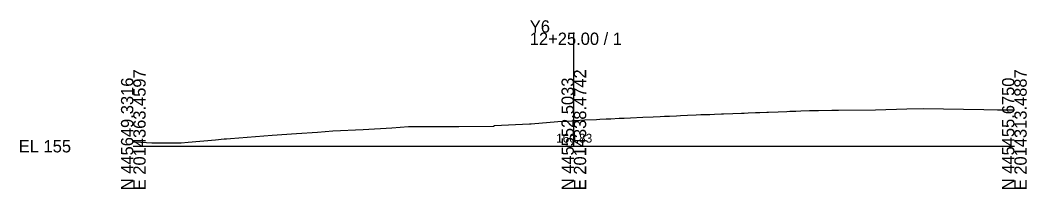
# Model space of a CAD drawing. Extents: x -26 to 203, y -10 to 4529.
# Drawn here: x -25.7 to 202.8, y 4490.3 to 4528.7 of the extents above; entities that cross this region are included whole.
import ezdxf

# ---------------------------------------------------------------- set-up
doc = ezdxf.new("R2010")
doc.units = 0
for name, color, linetype in [('Default', 7, 'Continuous'), ('Exist Cross Section Cell', 7, 'Continuous'), ('Exist XS Center Line Elevation Label', 7, 'Continuous'), ('Exist XS Ground Line', 7, 'Continuous')]:
    doc.layers.add(name, color=color, linetype=linetype)

msp = doc.modelspace()

# ---------------------------------------------------------------- linework, layer by layer
at = {"layer": 'Exist Cross Section Cell'}
for p, q in [((100, 4500), (100, 4525.83)), ((0, 4500), (100, 4500)), ((100, 4500), (200, 4500))]:
    msp.add_line(p, q, dxfattribs=at)
at = {"layer": 'Exist XS Ground Line'}
msp.add_lwpolyline([(0, 4500.96), (0.52, 4500.98), (4.24, 4500.78), (10.85, 4500.8), (12.45, 4500.93), (18.68, 4501.46), (20.66, 4501.66), (21.18, 4501.69), (22.04, 4501.74), (31.5, 4502.54), (37.08, 4502.91), (41.83, 4503.2), (45.3, 4503.51), (52.16, 4503.81), (58.71, 4504.21), (62.49, 4504.46), (73.91, 4504.49), (81.79, 4504.6), (82.01, 4504.74), (89.9, 4505.07), (90.28, 4505.1), (96.39, 4505.59), (97.49, 4505.67), (98.4, 4505.73), (99.56, 4505.8), (100, 4505.83), (100.62, 4505.87), (100.92, 4505.88), (101.39, 4505.91), (102.51, 4505.97), (105.11, 4506.09), (105.9, 4506.13), (107.34, 4506.2), (107.73, 4506.22), (108.37, 4506.25), (110.3, 4506.35), (111.42, 4506.4), (112.85, 4506.48), (115.69, 4506.62), (118.01, 4506.71), (119.62, 4506.79), (120.61, 4506.83), (121.68, 4506.87), (123.33, 4506.95), (124.22, 4506.98), (125.8, 4507.07), (127.74, 4507.14), (128.86, 4507.18), (130.3, 4507.23), (130.89, 4507.25), (131.92, 4507.29), (133.5, 4507.34), (133.98, 4507.36), (136.11, 4507.44), (138.08, 4507.52), (138.66, 4507.54), (139.59, 4507.58), (141.21, 4507.64), (142.19, 4507.67), (143.81, 4507.74), (144.22, 4507.76), (146.4, 4507.84), (148.37, 4507.92), (149, 4507.94), (150.39, 4508), (151.5, 4508.04), (153.46, 4508.12), (154.67, 4508.15), (155.56, 4508.16), (158.58, 4508.2), (160.05, 4508.2), (168.48, 4508.27), (175.61, 4508.54), (179.29, 4508.61), (193.07, 4508.34), (196.15, 4508.31), (197.49, 4508.31), (200, 4508.28)], dxfattribs=at)

# ---------------------------------------------------------------- texts
at = {"layer": 'Default'}
msp.add_text('-', height=0.0001, dxfattribs=at).set_placement((0, 4500))
at = {"layer": 'Exist Cross Section Cell'}
for s, p in [('Y6', (90, 4525.83)), ('12+25.00 / 1', (90, 4523.03)), ('EL 155', (-26, 4498.6))]:
    msp.add_text(s, height=2.8, dxfattribs=at).set_placement(p)
for s, p in [('E 2014363.4597', (2.8, 4490)), ('E 2014338.4742', (102.8, 4490)), ('E 2014313.4887', (202.8, 4490)), ('N 445649.3316', (0, 4490)), ('N 445552.5033', (100, 4490)), ('N 445455.6750', (200, 4490))]:
    msp.add_text(s, height=2.8, rotation=90, dxfattribs=at).set_placement(p)
at = {"layer": 'Exist XS Center Line Elevation Label'}
msp.add_text('160.83', height=2, dxfattribs=at).set_placement((95.99, 4500.83))

doc.saveas('drawing.dxf')
